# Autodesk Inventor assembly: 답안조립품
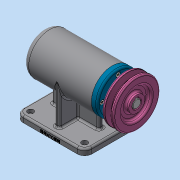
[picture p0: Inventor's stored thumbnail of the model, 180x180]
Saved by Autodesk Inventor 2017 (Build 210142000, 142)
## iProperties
Part Number: 답안조립품
Material: 일반
Document SubType Name: Assembly
Designer: mrc
Author: mrc
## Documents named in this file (12)
- C:\Users\mrc\Desktop\701004V1020\답안조립품.iam
- C:\Users\mrc\Desktop\701004V1020\본체.ipt
- C:\Users\mrc\Desktop\701004V1020\축.ipt
- C:\Users\mrc\Desktop\701004V1020\커버.ipt
- C:\Users\mrc\Desktop\701004V1020\키 5 x 5 x 16.ipt
- C:\Users\mrc\Desktop\701004V1020\오일 실.ipt
- C:\Users\mrc\Desktop\701004V1020\베어링 51202.ipt
- C:\Users\mrc\Desktop\701004V1020\베어링 6004.ipt
- C:\Users\mrc\Desktop\701004V1020\어댑터슬리브.ipt
- C:\Users\mrc\Desktop\701004V1020\볼트 M4.ipt
- C:\Users\mrc\Desktop\701004V1020\멈춤나사 M3.ipt
- C:\Users\mrc\Desktop\701004V1020\V벨트풀리.ipt
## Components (1 placed, 1 different names)
1. V벨트풀리:1
